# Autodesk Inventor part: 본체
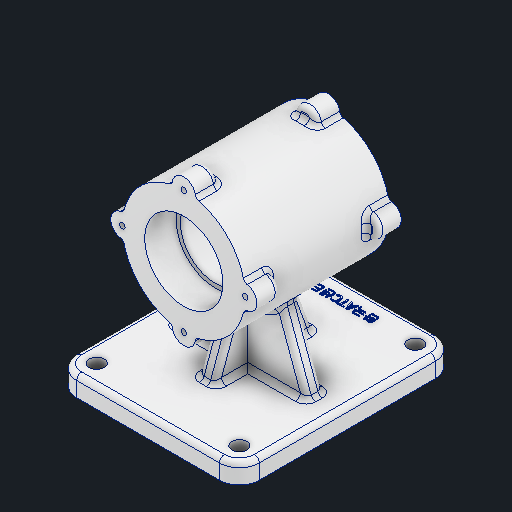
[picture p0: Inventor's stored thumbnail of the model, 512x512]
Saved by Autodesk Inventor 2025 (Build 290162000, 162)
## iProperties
Created: 2025-08
Part Number: 본체
Material: 알루미늄 6061
Document SubType Name: Modeling
Designer: infra08
Density: 2.7 g/cm^3
Appearance: 알루미늄 - 평지
Mass: 1223.04 g
Surface Area: 803.281 cm^2
Volume: 452.979 cm^3
Author: infra08
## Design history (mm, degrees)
sketch "스케치1"
  geometry: L1 (55, 65)-(-55, 65); L2 (-55, 65)-(-55, -65); L3 (-55, -65)-(55, -65); L4 (55, -65)-(55, 65); L5 (55, 65)-(-55, -65); L6 (-55, 65)-(55, -65); C1 r 4.5 at (-43, 53); C2 r 4.5 at (-43, -53); C3 r 4.5 at (43, -53); C4 r 4.5 at (43, 53); 2 further points
  constraints: 12 end point, 4 centre point, 2 horizontal alignment, 2 midpoint, 2 parallel, 2 vertical alignment, 1 coincident, 1 horizontal, 1 perpendicular
  dimensions: "d0" = 130 distance of L1.end L2.end; "d1" = 110 distance of L2.end L3.end; "d3" = 9 diameter of C1; "d4" = 9 diameter of C3; "d5" = 9 diameter of C2; "d6" = 12 distance from line of C1.centre L1; "d7" = 12 distance from line of L3 C2.centre (= d6); "d8" = 12 distance from line of L2 C1.centre (= d6); "d9" = 12 distance from line of L4 C3.centre; "d10" = 9 diameter of C4
extrude "돌출1" new body sketch "스케치1" distance "d11" = 12; taper "d12" = 0 deg
sketch "스케치2"
  geometry: L1 (70, 43.5)-(107, 43.5); L2 (107, -43.5)-(70, -43.5); L3 (70, -43.5)-(70, 43.5); L4 (93.5, 43.5)-(93.5, 24.5); L5 (93.5, 24.5)-(91, 24.5); L6 (91, 24.5)-(91, -24.5); L7 (91, -24.5)-(93.5, -24.5); L8 (93.5, -24.5)-(93.5, -43.5); L9 (107, 43.5)-(107, -43.5); L10 (0, 65)-(0, -65) reference; L11 (-12, -65)-(-12, 65) reference; 2 further points
  constraints: 18 end point, 4 perpendicular, 4 point on line, 2 vertical, 1 horizontal, 1 midpoint
  dimensions: "d13" = 87 distance between parallel lines of L2 L1; "d14" = 19 distance of L4.start L4.end; "d15" = 19 distance of L7.end L8.end (= d14); "d16" = 37 distance between parallel lines of L3 L9; "d17" = 23.5 distance between parallel lines of L3 L4; "d18" = 21 distance between parallel lines of L3 L6; "d19" = 43.5 distance from line of point (0, 0) L1 (= 0.5 x d13); "d20" = 82 distance between parallel lines of L11 L3
revolve "회전1" sketch "스케치2" stored, may be unused: angle "d21" = 90 deg
sketch "스케치3"
  geometry: C1 r 7 at (0, 37); 4 further points
  constraints: 1 centre point, 1 vertical alignment, 2 other
  dimensions: "d22" = 14 diameter of C1
extrude "돌출2" join sketch "스케치3" distance "d23" = 14; taper "d24" = 0 deg
sketch "스케치4"
  geometry: A1 r 7 centre (0, 0) between (6.969, -0.662) and (-6.969, -0.662) reference; 1 further point
hole "구멍1" sketch "스케치4" at (0, 0) diameter "d25" = 3.242; stored, may be unused: countersink angle "d29" = 90 deg, drill point angle "d31" = 118 deg; dims "d26" = 8, "d27" = 4, "d28" = 2, "d30" = 10
sketch "스케치5"
  geometry: L1 (0, -30)-(33, -17.989); L2 (0, -65)-(0, -30); L3 (31.379, 43.5)-(34.621, 43.5) reference; L4 (33, -29.5)-(33, 29.5) reference; L5 (33, 0)-(0, 0); L6 (0, 30)-(33, 17.989); 1 further point
  constraints: 8 end point, 2 midpoint, 2 symmetric about line, 2 vertical alignment, 1 horizontal, 1 vertical
  dimensions: "d36" = 110 deg angle of L2 L1; "d37" = 30 distance of L5.end L1.start
sketch "스케치7"
  geometry: L1 (55, 0)-(-55, 0) reference; L2 (-41, 0)-(-25.336, 43.036); L3 (-25.336, 43.036)-(-25.336, 0); L4 (-55, 0)-(55, 0) reference; L5 (0, 26)-(0, 0); A1 r 37 centre (0, 70) between (-36.338, 63.031) and (-6.969, 33.662) reference; A2 r 7 centre (0, 33) between (-6.969, 33.662) and (6.969, 33.662) reference
  constraints: 6 end point, 2 point on circle, 2 point on line, 1 perpendicular, 1 vertical
  dimensions: "d47" = 14 distance of L1.end L2.start; "d48" = 110 deg angle of L1 L2
sketch "스케치6"
  geometry: L1 (-5, 17.989)-(5, 17.989); L2 (5, 17.989)-(5, -17.989); L3 (5, -17.989)-(-5, -17.989); L4 (-5, -17.989)-(-5, 17.989); L5 (-5, 17.989)-(5, -17.989); L6 (5, 17.989)-(-5, -17.989); L7 (-25.336, 5)-(25.336, 5); L8 (25.336, 5)-(25.336, -5); L9 (25.336, -5)-(-25.336, -5); L10 (-25.336, -5)-(-25.336, 5); L11 (-25.336, 5)-(25.336, -5); L12 (25.336, 5)-(-25.336, -5); L13 (0, 30)-(0, 17.989) reference; L14 (-41, 0)-(-25.336, 0) reference; L15 (-25.336, 0)-(25.336, 0); L16 (25.336, 0)-(25.336, -10); L17 (25.336, -10)-(-25.336, -10); L18 (-25.336, -10)-(-25.336, 0); L19 (-25.336, 0)-(25.336, -10); L20 (25.336, 0)-(-25.336, -10); L21 (-55, 65)-(55, 65) reference; 15 further points
  constraints: 36 end point, 10 midpoint, 6 parallel, 4 coincident, 3 horizontal, 3 perpendicular, 2 vertical alignment
  dimensions: "d38" = 10 distance between parallel lines of L4 L2; "d49" = 10 distance between parallel lines of L7 L9; "d66" = 70 distance from line of point (0, -5) L21; "d67" = 10 distance of L17.end L15.start
extrude "돌출3" join sketch "스케치6" stored distance "d39" = 14; taper "d40" = 0 deg
feature "리브1" dims "d41" = 1, "d42" = 10, "d43" = 0, "d44" = 0, "d45" = 1, "d46" = 1
feature "리브3" dims "d56" = 1, "d57" = 10, "d58" = 0, "d59" = 0, "d60" = 1, "d61" = 1
feature "리브4" dims "d68" = 1, "d69" = 10, "d70" = 0, "d71" = 0, "d72" = 1, "d73" = 1
fillet "모깎기1" dims "d62" = 12
fillet "모깎기3" dims "d64" = 3
sketch "스케치8" dims "d0" = 130, "d1" = 110, "d3" = 9, "d4" = 9, "d5" = 9, "d6" = 12, "d7" = 12 (= d6), "d8" = 12 (= d6), "d9" = 12, "d10" = 9
  geometry: L1 (21.187, 50.113)-(-21.187, 50.113); L2 (-21.187, 50.113)-(-21.187, 55.887); L3 (-21.187, 55.887)-(21.187, 55.887); L4 (21.187, 55.887)-(21.187, 50.113); L5 (41, 0)-(41, -10) reference; 4 further points
  constraints: 3 midpoint, 1 vertical alignment, 2 other
  dimensions: "d74" = 58 vertical distance of point (21.187, 53) point (41, -5)
feature "엠보싱1" sketch "스케치8" dims "d13" = 87, "d14" = 19, "d15" = 19 (= d14), "d16" = 37, "d17" = 23.5, "d18" = 21, "d19" = 43.5 (= 0.5 x d13), "d20" = 82, "d75" = 0.5, "d76" = 0
fillet "모깎기4" dims "d77" = 3
node "솔리드1"
pattern_circular "원형 패턴1" dims "d33" = 360 deg
mirror "미러1"
mirror "미러3"
feature "A9D066F2-1C7D-4E18-AEED-F7BC21143FA4" dims "d25" = 3.242, "d26" = 8, "d27" = 4, "d28" = 2, "d29" = 90 deg, "d30" = 10, "d31" = 118 deg
